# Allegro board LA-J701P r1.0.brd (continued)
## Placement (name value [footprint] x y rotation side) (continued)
PCB12  0.1U_0402_25V6  [C_0402]  48.06 3.45 180 bottom
PCB13  10U_0603_25V6M  [C_0603]  71.16 16.66 0 top
PCB14  10U_0603_25V6M  [C_0603]  71.16 15.39 0 top
PCB15  0.68U_0805_50V7K  [C_0805]  51.08 11.7 0 bottom
PCB16  1U_0402_25V6K  [C_0402]  51.92 5.38 0 bottom
PCB17  10U_0603_25V6M  [C_0603]  71.16 14.12 0 bottom
PCB18  2.2U_0402_10V6M  [C_0402]  48.03 11.82 180 bottom
PCB19  0.047U_0402_25V7K  [C_0402]  44.43 9.97 90 bottom
PCB20  680P_0402_50V7K  [C_0402]  63.48 4.72 90 top
PCB21  680P_0402_50V7K  [C_0402]  64.44 4.69 90 top
PCB22  0.1U_0402_25V6  [C_0402]  43.03 7.71 0 bottom
PCB23  0.1U_0402_25V6  [C_0402]  42.83 6.83 270 bottom
PCB24  0.1U_0402_25V6  [C_0402]  43.67 5.07 0 bottom
PCB25  100P_0402_50V8J  [C_0402]  51.74 4.46 0 bottom
PCB26  10U_0603_25V6M  [C_0603]  71.16 15.39 0 bottom
PCB27  10U_0603_25V6M  [C_0603]  71.16 16.66 0 bottom
PCB28  680P_0402_50V7K  [C_0402]  43.59 1.67 0 bottom
PCB29  15P_0402_50V8J  [C_0402]  44.42 3.52 270 bottom
PCB30  1800P_0402_50V7K  [C_0402]  45.34 1.66 0 bottom
PCB31  33P_0402_50V8J  [C_0402]  46.21 3.52 270 bottom
PCB32  100P_0402_50V8J  [C_0402]  51.31 3.57 0 bottom
PCB33  0.1U_0402_6.3V7K  [C_0402]  52.96 5.25 0 top
PCB34  1U_0402_25V6K  [C_0402]  76.03 6.01 270 top
PCB35  10U_0603_25V6M  [C_0603]  73.43 5.89 0 top
PCD1  4700P_0402_50V7K  [C_0402]  24.88 74.76 180 bottom
PCD2  100P_0402_50V8J  [C_0402]  32.67 74.19 0 bottom
PCD3  100P_0402_50V8J  [C_0402]  33.43 70.12 0 bottom
PCD4  1000P_0402_50V7K  [C_0402]  33.43 71.14 0 bottom
PCD5  2200P_0402_25V7K  [C_0402]  30.77 70.22 180 bottom
PCD6  0.1U_0402_25V6  [C_0402]  23.56 64.51 90 bottom
PCM1  22U_0603_6.3V6M  [C_0603]  146 38.98 180 bottom
PCM2  0.1U_0402_10V7K  [C_0402]  164.87 56.87 0 bottom
PCM3  22U_0603_6.3V6M  [C_0603]  150.37 32.19 0 bottom
PCM4  0.1U_0402_25V6  [C_0402]  158.27 39.79 270 top
PCM5  1U_0402_6.3V6K  [C_0402]  164.24 53.45 0 bottom
PCM6  22U_0603_6.3V6M  [C_0603]  146 36.57 180 bottom
PCM7  10U_0603_25V6M  [C_0603]  157.78 39.97 270 bottom
PCM8  22U_0603_6.3V6M  [C_0603]  150.37 33.39 0 bottom
PCM9  10U_0603_25V6M  [C_0603]  157.18 39.98 270 top
PCM10  1U_0402_6.3V6K  [C_0402]  163.38 50.32 90 bottom
PCM11  680P_0402_50V7K  [C_0402]  154.5 37.95 270 top
PCM12  2200P_0402_50V7K  [C_0402]  159.1 39.97 270 bottom
PCM13  0.1U_0402_10V7K  [C_0402]  164.24 55.95 0 bottom
PCM14  0.1U_0402_25V6  [C_0402]  157.56 52.57 0 bottom
PCM15  22U_0603_6.3V6M  [C_0603]  146 37.78 180 bottom
PCM16  22U_0603_6.3V6M  [C_0603]  150.37 34.6 0 bottom
PCM17  0.033U_0402_16V7K  [C_0402]  161.46 58.37 90 bottom
PCM18  10U_0402_6.3V6M  [C_0402]  159.17 58.12 0 bottom
PCM19  10U_0402_6.3V6M  [C_0402]  159.17 59.07 0 bottom
PCS1  2200P_0402_25V7K  [C_0402]  26.03 56.14 270 top
PD2  30MA_30V_0.5UA_0.4V_SOD323-2  [RB751V-40_SOD323-2]  84.32 11.97 90 top
PDB1  -  [BAT54CW_SOT323-3]  53.83 11.47 90 top
PDD1  -  [BZT52-B5V1S_SOD323-2]  29.95 60.41 90 bottom
PDM1  30MA_30V_0.5UA_0.4V_SOD323-2  [D_SOD323-2]  162.03 51.67 270 bottom
PF2  12A_24V_F1206HB12V024TM  [F_F1206HB12V024TM]  74.95 12.33 270 bottom
PFD1  7A_24V_F1206HI7000V024TM  [F_F1206HI7000V024TM]  28.22 74.95 0 bottom
PFS1  7A_24V_F1206HI7000V024TM  [F_F1206HI7000V024TM]  30.41 56.63 180 bottom
PH1  100K +-1% 0402 B25/50 4250K  [R_0402]  122.06 55.35 270 top
PH801  100K_0402_1%_B25/50 4250K  [R_0402]  111.67 93.1 90 bottom
PH802  100K_0402_1%_B25/50 4250K  [R_0402]  85.4 93.43 90 bottom
PJ251  -  [JUMP_43X79]  123.85 10.46 180 top
PJ252  -  [JUMP_43X79]  111.1 8.1 90 top
PJ301  -  [JUMP_43X79]  181.01 65.81 135 top
PJ302  -  [JUMP_43X118]  171.52 60.78 135 bottom
PJ303  -  [JUMP_43X39]  170.26 69.45 45 top
PJ501  -  [JUMP_43X118]  44.83 14.9 180 bottom
PJ502  -  [JUMP_43X118]  24.98 14.39 90 top
PJ503  -  [JUMP_43X39]  32.49 8.88 180 top
PJ601  -  [JUMP_43X118]  151.14 82.28 225 bottom
PJ604  -  [JUMP_43X79]  157.83 96.21 315 bottom
PJ1803  -  [JUMP_43X79]  173.18 87.74 225 bottom
PJ1804  -  [JUMP_43X79]  162.19 72.95 225 bottom
PJM1  -  [JUMP_43X79]  159.98 42.37 180 bottom
PJM2  -  [JUMP_43X118]  146.85 32.99 270 bottom
PJM3  -  [JUMP_43X39]  158.94 60.64 180 bottom
PL3  -  [5A_Z80_0805_2P]  73 5.31 270 bottom
PL4  -  [5A_Z80_0805_2P]  74.91 5.31 270 bottom
PL301  1.5UH_6A_20%_5X5X3_M  [L_5X5X3_M]  178.11 65.82 225 bottom
PL501  1.5UH_9A_20%_7X7X3_M  [L_7X7X3_M]  32.21 14.62 180 bottom
PL602  1UH_6.6A_20%_5X5X3_M  [L_5X5X3_M_2P]  156.21 90.01 225 bottom
PL801  NA_2P  [5A_Z80_0805_2P]  86.78 103.69 90 bottom
PL802  NA_2P  [5A_Z80_0805_2P]  88.62 103.69 90 bottom
PL803  0.24UH_22A_+-20%_7X7X3_M  [L_7X7X3_M]  81.14 96.9 270 bottom
PL804  0.15UH_NA__35A_20%  [L_7X7X3_M]  113.54 92.98 0 bottom
PL805  0.15UH_NA__35A_20%  [L_7X7X3_M]  130.34 95.63 270 bottom
PL806  0.15UH_NA__35A_20%  [L_7X7X3_M]  145.77 95.5 270 bottom
PL1802  1.5UH_TMPC0412HP-1R5M-Z02_3A_20%  [TAI-T_TMPC0412HP-1R5M-Z02_2P]  166.7 77.43 225 bottom
PLB1  2.2UH_PCMB103T-2R2MS_13A_20%  [CYNTE_PCMB103T-2R2MS_2P]  59.78 9.77 0 bottom
PLD11  -  [5A_Z80_0805_2P]  31.98 73 270 bottom
PLM1  1UH_6.6A_20%_5X5X3_M  [L_5X5X3_M]  149.48 36.47 90 bottom
PQ601  -  [LSK3541G1ET2L_VMT3]  166.21 90.84 135 top
PQ801  AON6994_DFN5X6D-8-7  [AON6962_DFN5X6D-8-7]  83.81 104.13 270 bottom
PQ802  -  [AON6962_DFN5X6D-8-7]  112.59 97.79 90 bottom
PQ804  -  [AON6962_DFN5X6D-8-7]  133.75 101.62 270 bottom
PQ805  -  [AON6962_DFN5X6D-8-7]  143.08 97.9 90 bottom
PQB1  AON6962_DFN5X6D-8-7  [AON6992_DFN5X6D-8-7]  57.26 11.7 270 top
PQB2  -  [AON6994_DFN5X6D-8-7]  70.5 7.89 90 top
PQB3  -  [LSK3541G1ET2L_VMT3]  53.47 7.26 0 top
PQB4  -  [LSK3541G1ET2L_VMT3]  54.69 4.79 90 top
PQB13  AONR21357_P_DFN33-8-5  [Q_P_DFN33-8-5]  72.44 12.42 270 top
PQD3  -  [2N7002KDW_SOT363-6]  25.87 64.46 180 bottom
PQD4  TP0610K-T1-GE3 1P SOT23-3  [LBSS84LT1G_SOT23-3]  29.98 65.17 270 bottom
PQD5  -  [METR3906KW-G_SOT363-6]  26.31 61.47 0 bottom
PQD11  AONR21357_P_DFN33-8-5  [Q_P_DFN33-8-5]  32.27 68.56 0 bottom
PQD12  AONR21357_P_DFN33-8-5  [Q_P_DFN33-8-5]  34.23 60.75 180 bottom
PQM1  -  [AON7408L_DFN8-5]  153.29 40.49 90 bottom
PQM2  -  [AON7506_DFN3X3-8-5]  156.16 38.6 270 bottom
PQS2  L2N7002SWT1G 1N SC-70-3  [L2N7002WT1G_SC70-3]  26.08 52.88 180 top
PQS3  TP0610K-T1-GE3 1P SOT23-3  [LBSS84LT1G_SOT23-3]  29.68 53.06 180 top
PQS4  -  [METR3906KW-G_SOT363-6]  32.41 50.95 0 top
PQS11  AONR21357_P_DFN33-8-5  [Q_P_DFN33-8-5]  28.33 57.44 270 top
PQS12  AONR21357_P_DFN33-8-5  [Q_P_DFN33-8-5]  36.04 55.47 90 top
PR8  0_0603_5%  [R0603_0OHM]  81.77 12.21 180 top
PR9  45.3K_0603_1%  [R_0603]  81.58 13.48 0 top
PR10  0_0603_5%  [R0603_0OHM]  81.79 11.01 180 top
PR11  100_0402_1%  [R_0402]  82.88 15.73 90 bottom
PR12  100_0402_1%  [R_0402]  81.92 15.73 90 bottom
PR13  16.5K_0402_1%  [R_0402]  122.07 57.24 270 top
PR14  200K_0402_1%  [R_0402]  85.11 15.65 180 bottom
PR15  10K_0402_5%  [R_0402]  85.11 16.44 180 bottom
PR251  0_0402_5%  [R0402_0OHM]  126.25 8.51 180 top
PR252  43K_0402_1%  [R_0402]  113.86 8.57 0 top
PR254  20K_0402_1%  [R_0402]  114.77 7.78 180 top
PR256  0_0402_5%  [R_0402]  126.28 7.7 180 top
PR301  0_0402_5%  [R0402_0OHM]  177.32 65.51 315 top
PR302  4.7_1206_5%  [R_1206]  176.31 62.68 225 top
PR303  100K_0402_5%  [R_0402]  177.58 71.07 225 top
PR304  1K_0402_1%  [R_0402]  172.39 70.78 315 top
PR501  0_0402_5%  [R0402_0OHM]  35.11 16.74 90 bottom
PR502  4.7_0805_5%  [R_0805]  31.72 12.46 270 top
PR503  0_0402_5%  [R_0402]  39.23 8.9 90 bottom
PR504  499K_0402_1%  [R_0402]  178.29 72.15 135 top
PR505  1K_0402_1%  [R_0402]  38.12 10.22 180 bottom
PR506  150K_0402_1%  [R_0402]  177.05 71.64 135 top
PR507  100K_0402_5%  [R_0402]  171.23 68.28 225 top
PR508  0_0402_5%  [R0402_0OHM]  169.36 65.14 135 top
PR509  2.2K_0402_5%  [R_0402]  172.29 72.34 225 top
PR510  0_0402_5%  [R0402_0OHM]  173.73 73.35 225 top
PR511  100K_0402_5%  [R_0402]  169.28 66.34 315 top
PR512  1M_0402_1%  [R_0402]  173.69 72.1 45 top
PR601  0_0402_5%  [R0402_0OHM]  166.27 90.84 135 bottom
PR602  4.7_1206_5%  [R_1206]  153.44 92.82 225 bottom
PR603  0_0603_5%  [R0603_0OHM]  157.31 92.73 135 bottom
PR604  0_0402_5%  [R0402_0OHM]  160.73 87.44 225 bottom
PR605  0_0402_5%  [R_0402]  163.76 89.62 315 bottom
PR606  10K_0402_1%  [R_0402]  163.18 89.03 315 bottom
PR607  1M_0402_1%  [R_0402]  164.39 90.25 315 bottom
PR609  36.5K_0402_1%  [R_0402]  162.61 88.47 315 bottom
PR610  10_0402_1%  [R_0402]  153.53 78.99 315 bottom
PR611  1K_0402_1%  [R_0402]  161.19 84.25 315 bottom
PR621  0_0402_5%  [R_0402]  165.39 92.01 45 top
PR622  0_0402_5%  [R_0402]  164.67 89.5 45 top
PR623  0_0402_5%  [R_0402]  166.84 91.4 135 bottom
PR713  0_0402_5%  [R0402_0OHM]  167.42 80.68 135 bottom
PR716  1K_0402_1%  [R_0402]  172.71 76.37 135 bottom
PR719  0_0402_5%  [R_0402]  169.32 76.81 45 top
PR720  0_0402_5%  [R0402_0OHM]  169.42 77.99 225 top
PR801  10_0402_5%  [R_0402]  106.87 94.49 90 bottom
PR802  10_0402_5%  [R_0402]  104.46 95.33 270 bottom
PR803  0_0603_5%  [R0603_0OHM]  84.94 103.97 180 top
PR804  2.2_0603_5%  [R_0603]  94.12 103.02 90 bottom
PR805  10K_0402_1%  [R_0402]  103.67 95.33 270 bottom
PR806  63.4K_0402_1%  [R_0402]  102.43 94.8 270 bottom
PR807  105K_0402_1%  [R_0402]  104.04 102.19 0 bottom
PR808  4.7_1206_5%  [R_1206]  81.84 97.77 180 top
PR809  2.43K_0402_1%  [R_0402]  91.23 98.71 0 top
PR810  845_0402_1%  [R_0402]  92.18 97.76 180 bottom
PR811  2.2_0402_5%  [R_0402]  101.24 101.66 0 top
PR812  10_0603_5%  [R_0603]  92.22 91.27 180 bottom
PR815  0_0402_5%  [R0402_0OHM]  94.86 90.63 90 bottom
PR816  9.31K_0402_1%  [R_0402]  101.07 91.6 180 bottom
PR817  0_0603_5%  [R0603_0OHM]  110.93 96.35 0 bottom
PR818  8.25K_0402_1%  [R_0402]  96.62 91.54 180 bottom
PR819  100K_0402_1%  [R_0402]  92.12 101.25 180 bottom
PR820  2.2_0603_5%  [R_0603]  102.21 103.03 90 bottom
PR821  11.5K_0402_1%  [R_0402]  100.18 90.74 0 bottom
PR822  11.8K_0402_1%  [R_0402]  96.62 90.71 180 bottom
PR823  14.3K_0402_1%  [R_0402]  97.58 91.44 180 top
PR824  4.7_1206_5%  [R_1206]  115.51 95.67 0 top
PR825  15K_0402_1%  [R_0402]  100.12 91.48 0 top
PR826  2K_0402_1%  [R_0402]  104.97 101.43 180 bottom
PR827  100K_0402_1%  [R_0402]  94.59 95.6 0 top
PR828  100K_0402_5%  [R_0402]  92.12 100.43 180 bottom
PR829  10K_0402_5%  [R_0402]  92.12 99.6 180 bottom
PR830  1.1K_0402_1%  [R_0402]  104.09 99.75 0 bottom
PR831  59K_0402_1%  [R_0402]  91.25 93.36 90 bottom
PR832  10K_0402_1%  [R_0402]  91.25 95.08 90 bottom
PR833  10_0402_5%  [R_0402]  91.23 96.87 0 top
PR834  13.7K_0402_1%  [R_0402]  91.41 92.92 0 top
PR835  205K_0402_1%  [R_0402]  94 91.52 270 bottom
PR836  470_0402_1%  [R_0402]  93.13 90.56 90 top
PR837  33K_0402_1%  [R_0402]  93.18 91.52 270 bottom
PR838  0_0603_5%  [R0603_0OHM]  132.08 103.09 0 bottom
PR839  2.2_0603_5%  [R_0603]  96.81 103.02 90 bottom
PR840  4.7_1206_5%  [R_1206]  133.3 96.63 180 top
PR841  2K_0402_1%  [R_0402]  104.92 97.92 180 top
PR842  1.1K_0402_1%  [R_0402]  104.16 98.84 0 bottom
PR843  0_0402_5%  [R_0402]  104.05 96.25 0 top
PR844  0_0402_5%  [R0402_0OHM]  104.11 96.37 0 bottom
PR845  0_0402_5%  [R_0402]  103.99 97.11 0 top
PR846  0_0402_5%  [R0402_0OHM]  104.11 97.17 0 bottom
PR847  0_0402_5%  [R0402_0OHM]  147.8 103.68 90 bottom
PR853  0_0603_5%  [R_0603]  143.02 99.37 270 top
PR855  4.7_1206_5%  [R_1206]  145.08 95.27 0 top
PR856  2K_0402_1%  [R_0402]  109.03 96.37 90 top
PR857  1.1K_0402_1%  [R_0402]  105.74 96.26 0 top
PR858  24.3K_0402_1%  [R_0402]  99.3 90.54 90 top
PR859  21.5K_0402_1%  [R_0402]  97.44 90.67 90 bottom
PR860  2.2_0603_5%  [R_0603]  145.57 103.2 180 bottom
PR871  0_0402_5%  [R_0402]  51.65 2.37 0 bottom
PR1807  0_0402_5%  [R0402_0OHM]  173.95 77.63 135 top
PR1808  20K_0402_1%  [R_0402]  171.52 76.43 225 bottom
PR1809  10K_0402_1%  [R_0402]  172.7 77.62 315 bottom
PR1810  2.2_0603_5%  [R_0603]  165.38 80.15 225 bottom
PR1811  1M_0402_1%  [R_0402]  173.96 78.97 315 bottom
PR1812  100K_0402_1%  [R_0402]  169.47 74.57 315 bottom
PR1813  0_0402_5%  [R0402_0OHM]  93.06 92.92 0 top
PR1814  2.2_0402_1%  [R_0402]  105.96 103.85 270 bottom
PR1815  2.2_0402_1%  [R_0402]  99.8 92.84 90 top
PR1816  0_0402_5%  [R0402_0OHM]  94.97 92.84 90 top
PR1817  0_0402_5%  [R0402_0OHM]  96.94 94.51 270 top
PR1818  0_0402_5%  [R_0402]  96.18 94.51 270 top
PR1819  0_0402_5%  [R_0402]  92.74 93.68 0 top
PRB1  0.01_1206_1%  [R_1206_4P-D]  55.35 6.11 90 top
PRB2  4.99_0402_1%  [R_0402]  53.65 8.4 180 top
PRB3  4.99_0402_1%  [R_0402]  53.65 9.8 180 top
PRB4  0_0402_5%  [R0402_0OHM]  49.13 12.41 270 bottom
PRB5  511K_0402_1%  [R_0402]  48.06 1.67 180 bottom
PRB6  10_0402_1%  [R_0402]  51.26 5.66 0 top
PRB7  75K_0402_1%  [R_0402]  48.06 2.56 180 bottom
PRB8  1_0805_5%  [R_0805]  52.61 11.7 180 top
PRB9  0.01_1206_1%  [R_1206_4P-D]  75.81 7.64 180 top
PRB10  0_0402_5%  [R0402_0OHM]  50.56 2.49 180 bottom
PRB11  0_0402_5%  [R0402_0OHM]  45.37 11.85 0 bottom
PRB12  0_0402_5%  [R0402_0OHM]  50.57 1.59 180 bottom
PRB13  0_0402_5%  [R_0402]  50.52 3.52 180 bottom
PRB14  4.7_1206_5%  [R_1206]  59.6 5.05 0 top
PRB15  4.7_1206_5%  [R_1206]  68.32 5.05 180 top
PRB16  100K_0402_5%  [R_0402]  51.82 8.76 90 top
PRB17  100K_0402_5%  [R_0402]  51.06 8.43 180 top
PRB18  10_0402_1%  [R_0402]  43.67 6.85 0 bottom
PRB19  10_0402_1%  [R_0402]  43.67 5.96 0 bottom
PRB20  137K_0402_1%  [R_0402]  51.74 4.39 0 top
PRB21  10K_0402_1%  [R_0402]  43.54 3.52 270 bottom
PRB22  100K_0402_1%  [R_0402]  48.71 5.57 0 top
PRB23  82K_0402_1%  [R_0402]  50.52 6.83 270 top
PRB24  100K_0402_1%  [R_0402]  53.95 7.51 0 bottom
PRB25  165K_0402_1%  [R_0402]  52.35 6.22 90 bottom
PRB26  40.2K_0402_1%  [R_0402]  45.32 3.52 270 bottom
PRB27  100K_0402_1%  [R_0402]  51.31 6.85 0 top
PRB28  100K_0402_1%  [R_0402]  51.06 7.64 180 top
PRB29  100K_0402_5%  [R_0402]  54.16 3.62 180 bottom
PRB30  0_0402_5%  [R_0402]  53.14 6.22 90 bottom
PRB31  100K_0402_5%  [R_0402]  53.62 5.35 0 bottom
PRB32  0_0402_5%  [R0402_0OHM]  72.14 13.07 180 bottom
PRB33  100K_0402_5%  [R_0402]  47.88 5.28 270 top
PRB34  100K_0402_5%  [R_0402]  49.55 4.42 180 top
PRD1  499K_0402_1%  [R_0402]  30.79 69.31 180 bottom
PRD2  49.9K_0402_1%  [R_0402]  30 68.42 180 bottom
PRD3  47K_0402_1%  [R_0402]  25.27 60.31 180 bottom
PRD4  470K_0402_1%  [R_0402]  25.27 59.45 180 bottom
PRD5  47K_0402_1%  [R_0402]  28.55 60.9 90 bottom
PRD6  154K_0402_1%  [R_0402]  24.13 62.32 90 bottom
PRD7  24K_0402_1%  [R_0402]  24.98 63.23 0 bottom
PRD8  100K_0402_5%  [R_0402]  25.33 67.14 180 bottom
PRD9  470K_0402_1%  [R_0402]  28.5 62.63 180 bottom
PRM1  4.7_1206_5%  [R_1206]  151.81 39.45 0 top
PRM2  6.04K_0402_1%  [R_0402]  163.17 58.36 90 bottom
PRM3  0_0402_5%  [R0402_0OHM]  165.15 55.06 180 bottom
PRM4  0_0402_5%  [R0402_0OHM]  165.78 57.74 180 bottom
PRM5  23.7K_0402_1%  [R_0402]  160.73 50.3 90 bottom
PRM6  5.1_0603_5%  [R_0603]  165.73 52.37 180 bottom
PRM8  2.2_0603_5%  [R_0603]  165.7 51.14 180 bottom
PRM9  10K_0402_1%  [R_0402]  164 58.36 90 bottom
PRM10  470K_0402_1%  [R_0402]  165.15 54.27 180 bottom
PRM11  2.2_0603_5%  [R_0603]  157.33 53.55 90 bottom
PRM12  10_0402_5%  [R_0402]  162.36 59.29 270 bottom
PRM13  0_0402_5%  [R_0402]  163.16 60.06 90 bottom
PRM14  0_0402_5%  [R_0402]  163.99 60.06 90 bottom
PRS1  499K_0402_1%  [R_0402]  26.97 56.17 270 top
PRS2  49.9K_0402_1%  [R_0402]  26.92 53.98 180 top
PRS4  47K_0402_1%  [R_0402]  32.44 53.87 180 top
PRS5  470K_0402_1%  [R_0402]  33.3 53.87 0 top
PRS6  47K_0402_1%  [R_0402]  34.74 50.96 0 top
PU251  -  [RT9059GQW_WDFN10_3X3]  116.2 9.8 270 top
PU301  -  [SY8388BRHC_QFN16_2P5X2P5]  176.26 66.35 135 top
PU501  -  [SY8288CRAC_QFN20_3X3]  35.34 15.47 270 bottom
PU601  -  [SY8284RAC_QFN20_3X3]  158.92 92.14 315 bottom
PU801  RT3663BMGQW_WQFN52_6X6  [RT3663BHGQW_WQFN52_6X6]  100.54 99.39 180 bottom
PU802  -  [RT9610CGQW_WDFN8_2X2]  145.63 104.45 270 top
PU1802  -  [SY8386RHC_QFN16_2P5X2P5]  168.54 79.89 315 bottom
PUB1  BQ25710RSNR_QFN32_4X4  [BQ25700ARSNR_QFN32_4X4]  50.44 8.78 180 bottom
PUM1  -  [RT8207PGQW_WQFN20_3X3]  160.53 56.51 0 bottom
Q5  ME2320D-G 1N SOT-23-3  [LBSS138LT1G_SOT23-3]  159.59 70.1 315 bottom
Q146  -  [2N7002KW_SOT323-3]  160.36 66.36 135 bottom
Q201  -  [ME2301DC-G_SOT23-3]  56.47 64.92 270 top
Q202  -  [2N7002KDW_SOT363-6]  181.23 55.77 270 bottom
Q206  -  [LBSS139WT1G_SC70-3]  57.06 61.49 90 top
Q207  -  [LBSS139WT1G_SC70-3]  57.06 58.95 90 top
Q208  -  [ME2301DC-G_SOT23-3]  32.62 50.77 90 bottom
Q209  -  [ME2301DC-G_SOT23-3]  45.09 48.28 270 bottom
QA1  -  [ME2301DC-G_SOT23-3]  21.29 50.5 90 bottom
QA2  -  [ME2301DC-G_SOT23-3]  18.77 28.05 0 bottom
QA3  -  [ME2301DC-G_SOT23-3]  21.29 54.56 90 bottom
QA4  -  [2N7002KDW_SOT363-6]  17.81 22.23 0 bottom
QC1  -  [LBSS139WT1G_SC70-3]  78.4 57.55 90 top
QC2  -  [2N7002KDW_SOT363-6]  62.81 88.68 270 top
QH1  -  [2N7002KDW_SOT363-6]  17.74 70.97 0 top
QH2  2N7002KDW_SC88-6  [2N7002DW-T-R7_SOT363-6]  24.38 70.91 180 bottom
QKBL1  -  [ME2301DC-G_SOT23-3]  144.67 15.96 90 bottom
QT1  2N7002K_SOT23-3  [2N7002_SOT23-3]  18.3 77.5 180 top
QT2  -  [2N7002KW_SOT323-3]  30.42 69.36 270 top
QT3  -  [ME2301DC-G_SOT23-3]  42.75 78.5 270 top
QT4  -  [L2N7002WT1G_SC-70-3]  45.51 73.42 270 top
QTP1  -  [ME2301DC-G_SOT23-3]  121.92 8.4 270 bottom
QTS1  -  [MMST3904-7-F_SOT323-3]  74.53 17.54 90 bottom
QTS2  -  [MMST3904-7-F_SOT323-3]  19.98 47.25 0 bottom
QTS3  -  [MMST3904-7-F_SOT323-3]  98.56 88.09 90 bottom
R2  0_0805_5%  [R0805_0OHM]  54.21 70.41 90 top
R5  0_0402_5%  [R0402_0OHM]  58.65 76.42 270 top
R6  0_0402_5%  [R0402_0OHM]  53.39 74.57 180 top
R7  100K_0402_5%  [R_0402]  58.65 73.86 90 top
R8  100K_0402_5%  [R_0402]  54.38 74.57 0 top
R9  0_0805_5%  [R0805_0OHM]  50.97 78.01 0 top
R54  10K_0402_5%  [R_0402]  195.74 28.97 0 top
R55  100K_0402_5%  [R_0402]  182.35 47.44 90 top
R56  10K_0402_5%  [R_0402]  192.94 40.79 0 top
R57  10K_0402_5%  [R_0402]  186.03 47.44 90 top
R58  10_0402_5%  [R_0402]  173.66 39.39 180 top
R59  4.7K_0402_5%  [R_0402]  185.14 49.6 90 top
R60  47K_0402_5%  [R_0402]  179.11 27.78 270 top
R62  2.2K_0402_5%  [R_0402]  81.02 4.46 180 top
R63  2.2K_0402_5%  [R_0402]  81.02 5.28 180 top
R64  10K_0402_5%  [R_0402]  173.21 34.46 90 top
R65  100K_0402_5%  [R_0402]  193.77 31.76 180 top
R66  100K_0402_5%  [R_0402]  184.13 48.35 270 top
R67  100K_0402_5%  [R_0402]  189.72 48.35 270 top
R68  100K_0402_5%  [R_0402]  180.57 48.35 270 top
R69  100K_0402_5%  [R_0402]  193.98 43.64 180 top
R70  100K_0402_5%  [R_0402]  191 48.39 270 top
R74  100K_0402_1%  [R_0402]  182.39 54.23 90 bottom
R75  22_0603_1%  [R_0603]  178.24 57.08 0 bottom
R185  10K_0402_5%  [R_0402]  159.05 66.13 225 bottom
R201  150K_0402_5%  [R_0402]  60.94 64.86 270 top
R265  866_0402_1%  [R_0402]  182.01 22.59 270 top
R266  866_0402_1%  [R_0402]  158.42 25.48 180 bottom
R267  866_0402_1%  [R_0402]  177.46 27.72 270 top
R273  2.2K_0402_5%  [R_0402]  196.65 31.64 180 top
R274  2.2K_0402_5%  [R_0402]  196.65 32.4 180 top
R337  0_0603_5%  [R_0603]  47.17 62.84 0 top
R358  HCB1005KF-221T15  [MURAT_BLM15PX221SN1D_2P]  53.36 59.33 180 top
R359  0_0402_5%  [R0402_0OHM]  50.19 57.8 0 top
R360  0_0402_5%  [R_0402]  50.19 58.69 0 top
R2752  47K_0402_5%  [R_0402]  159.62 65.56 225 bottom
R3999  0_0402_5%  [R0402_0OHM]  177.91 47.44 90 top
R4000  0_0603_5%  [R0603_0OHM]  194.35 45.55 180 top
R4002  0_0402_5%  [R0402_0OHM]  187.05 47.44 90 top
R4006  100K_0402_5%  [R_0402]  57 78.2 270 top
R4007  100K_0402_5%  [R_0402]  61.83 63.95 90 top
R4010  10K_0402_5%  [R_0402]  179.68 47.44 90 top
R4011  10K_0402_5%  [R_0402]  178.79 47.44 90 top
R4012  10K_0402_5%  [R_0402]  175.56 46.79 90 top
R4014  1K_0402_5%  [R_0402]  54.21 58.68 90 top
R4015  10K_0402_5%  [R_0402]  51.63 54.2 270 top
R4020  10K_0402_5%  [R_0402]  172.22 31.16 180 top
R4021  4.7_1206_5%  [R_1206]  34.52 77.87 180 top
R4022  10K_0402_5%  [R_0402]  192.6 47.48 90 top
R4023  10K_0402_5%  [R_0402]  192.98 34.83 270 top
R4024  0_0402_5%  [R_0402]  55.92 62.32 270 top
R4025  0_0402_5%  [R_0402]  56.76 60.53 180 top
R4026  100K_0402_5%  [R_0402]  200.71 31.01 180 top
RA1  0_0603_5%  [R0603_0OHM]  28.83 5.74 90 bottom
RA2  33_0402_5%  [R_0402]  3.74 33.65 0 bottom
RA3  0_0603_5%  [R0603_0OHM]  22.6 6.8 90 bottom
RA4  33_0402_5%  [R_0402]  6.35 30.98 180 bottom
RA5  0_0603_5%  [R0603_0OHM]  28.35 2.27 180 bottom
RA6  0_0603_5%  [R0603_0OHM]  22.34 4.51 270 bottom
RA8  0_0402_5%  [R0402_0OHM]  10.16 30.93 0 bottom
RA9  10K_0402_5%  [R_0402]  11.41 40.66 90 bottom
RA10  2.2K_0402_5%  [R_0402]  9.63 41.45 180 bottom
RA11  2.2K_0402_5%  [R_0402]  7.5 41.55 270 bottom
RA12  0_0805_5%  [R0805_0OHM]  16.17 32.17 270 bottom
RA13  BLM15BD121SN1D_2P  [MURAT_BLM15BD121SN1D_2P]  10.79 42.13 180 top
RA14  BLM15BD121SN1D_2P  [MURAT_BLM15BD121SN1D_2P]  10.79 41.22 180 top
RA15  47_0402_5%  [R_0402]  7.01 44.98 0 bottom
RA16  47_0402_5%  [R_0402]  6.18 45 180 bottom
RA17  10K_0402_5%  [R_0402]  7.93 44.16 180 bottom
RA18  10K_0402_5%  [R_0402]  5.26 44.19 0 bottom
RA19  0_0603_5%  [R0603_0OHM]  14.01 36.59 125.1 top
RA21  0_0402_5%  [R0402_0OHM]  12.75 33.94 180 top
RA22  0_0402_5%  [R0402_0OHM]  16.82 54.42 90 bottom
RA23  0_0402_5%  [R0402_0OHM]  15.93 54.42 90 bottom
RA24  33K_0402_5%  [R_0402]  13.82 53.28 90 bottom
RA25  0_0402_5%  [R0402_0OHM]  3.79 36.34 90 bottom
RA26  0_0402_5%  [R0402_0OHM]  4.22 46.26 90 top
RA27  4.7K_0402_5%  [R_0402]  16.64 44.47 180 bottom
RA28  0_0402_5%  [R0402_0OHM]  2.68 39.4 0 top
RA29  4.7K_0402_5%  [R_0402]  16.64 45.26 180 bottom
RA30  0_0402_5%  [R_0402]  15.73 46.04 0 bottom
RA31  0_0402_5%  [R0402_0OHM]  17.09 51.57 180 top
RA32  0_0402_5%  [R0402_0OHM]  16.11 58.62 270 top
RA33  0_0402_5%  [R0402_0OHM]  13.38 30.55 90 bottom
RA34  0_0603_5%  [R0603_0OHM]  11.28 34.94 0 top
RA51  150K_0402_5%  [R_0402]  25.06 51.44 90 bottom
RA54  47K_0402_5%  [R_0402]  16.74 20.85 90 bottom
RA55  150K_0402_5%  [R_0402]  21.06 22.48 90 bottom
RA57  47K_0402_5%  [R_0402]  25.06 54.55 90 bottom
RA58  0_0402_5%  [R_0402]  19.54 50.45 270 bottom
RA59  0_0603_5%  [R_0603]  15.85 29.04 0 bottom
RA60  0_0402_5%  [R_0402]  19.54 54.58 270 bottom
RA61  47K_0402_5%  [R_0402]  20.23 22.48 90 bottom
RC1  1K_0402_5%  [R_0402]  112.69 44.85 90 bottom
RC2  1K_0402_5%  [R_0402]  113.58 58.76 270 top
RC4  4.7K_0402_5%  [R_0402]  80.75 64.29 270 top
RC5  2.2K_0402_5%  [R_0402]  77.32 57.35 90 top
RC6  100K_0402_5%  [R_0402]  81.39 58.2 270 top
RC8  100K_0402_5%  [R_0402]  86.8 59.2 180 bottom
RC9  100K_0402_5%  [R_0402]  77.45 61.5 270 top
RC10  100K_0402_5%  [R_0402]  86.9 67.81 180 bottom
RC11  10K_0402_5%  [R_0402]  90.73 56.6 180 top
RC12  10K_0402_5%  [R_0402]  90.73 55.33 180 top
RC13  10K_0402_5%  [R_0402]  90.73 57.42 180 top
RC14  10K_0402_5%  [R_0402]  90.73 54.37 180 top
RC15  1K_0402_5%  [R_0402]  87.05 56.6 180 top
RC16  1K_0402_5%  [R_0402]  87.05 55.71 180 top
RC17  1K_0402_5%  [R_0402]  84.57 58.37 180 bottom
RC18  1K_0402_5%  [R_0402]  86.8 58.37 180 bottom
RC21  0_0402_5%  [R0402_0OHM]  135.06 66.06 180 bottom
RC22  196_0402_1%  [R_0402]  98.8 73.16 180 top
RC24  4.7K_0402_5%  [R_0402]  139.63 81.43 180 bottom
RC25  4.7K_0402_5%  [R_0402]  121.23 80.12 270 bottom
RC28  1K_0402_5%  [R_0402]  84.67 53.23 90 bottom
RC29  1K_0402_5%  [R_0402]  132.69 65.22 90 bottom
RC30  220_0402_5%  [R_0402]  120.34 78.99 180 bottom
RC31  1K_0402_5%  [R_0402]  85.25 60.84 0 bottom
RC34  33_0402_5%  [R_0402]  142.85 63.82 90 bottom
RC35  33_0402_5%  [R_0402]  140.73 64.29 90 bottom
RC36  22K_0402_5%  [R_0402]  137.23 72.54 0 bottom
RC45  10K_0402_5%  [R_0402]  83.96 65.41 180 bottom
RC47  10K_0402_5%  [R_0402]  137.61 63.76 90 bottom
RC48  10K_0402_5%  [R_0402]  135.09 65.23 0 bottom
RC50  1K_0402_5%  [R_0402]  116.03 79.71 270 bottom
RC53  10K_0402_5%  [R_0402]  115.47 80.49 135 bottom
RC54  10K_0402_5%  [R_0402]  116.84 79.33 270 bottom
RC55  8.2K_0402_5%  [R_0402]  172.03 43.34 270 top
RC56  2.2K_0402_5%  [R_0402]  134.37 64.46 180 bottom
RC57  2.2K_0402_5%  [R_0402]  134.36 62.76 180 bottom
RC59  10K_0402_5%  [R_0402]  133.72 73.59 0 bottom
RC60  10K_0402_5%  [R_0402]  113.64 80.31 180 bottom
RC62  4.7K_0402_5%  [R_0402]  66.27 84.97 90 top
RC63  100K_0402_5%  [R_0402]  65.52 85.62 180 top
RC64  0_0402_5%  [R0402_0OHM]  168.19 42.35 270 top
RC65  2K_0402_5%  [R_0402]  133.72 74.43 0 bottom
RC66  2K_0402_5%  [R_0402]  112.73 78.5 0 bottom
RC67  33_0402_5%  [R_0402]  115.82 81.31 315 bottom
RC68  33_0402_5%  [R_0402]  135.37 74.45 0 bottom
RC69  33_0402_5%  [R_0402]  88.61 77.4 0 top
RC70  1K_0402_5%  [R_0402]  88.61 76.61 0 top
RC71  1K_0402_5%  [R_0402]  137.94 74.45 180 bottom
RC72  10K_0402_5%  [R_0402]  163.94 36.8 270 top
RC73  0_0402_5%  [R0402_0OHM]  165.26 34.56 0 top
RC74  33_0402_5%  [R_0402]  128.49 76.38 180 bottom
RC75  1M_0402_5%  [R_0402]  129.25 77.25 270 bottom
RC76  33_0402_5%  [R_0402]  128.49 77.2 180 bottom
RC77  10_0402_5%  [R_0402]  127.56 63.65 180 bottom
RC78  10_0402_5%  [R_0402]  128.32 66.63 180 bottom
RC79  10_0402_5%  [R_0402]  138.27 68.76 180 bottom
RC80  10_0402_5%  [R_0402]  128.58 67.39 180 bottom
RC81  22_0402_5%  [R_0402]  128.34 65.41 180 bottom
RC82  33_0402_5%  [R_0402]  128.13 69.86 180 bottom
RC83  100K_0402_5%  [R_0402]  172.7 37.48 0 top
RC84  10_0402_1%  [R_0402]  132.07 72.92 180 bottom
RC85  10K_0402_5%  [R_0402]  137.46 62.13 180 bottom
RC86  20M_0402_5%  [R_0402]  127.7 78.26 180 top
RC87  22 +-5% 0402  [R_0402]  140.38 62.84 270 bottom
RC89  10K_0402_5%  [R_0402]  83.02 67.01 0 bottom
RC90  10K_0402_5%  [R_0402]  134.38 60.33 90 bottom
RC91  10K_0402_5%  [R_0402]  189.32 16.4 0 top
RC92  10K_0402_5%  [R_0402]  140.69 43.66 270 bottom
RC93  10K_0402_5%  [R_0402]  138.15 54.3 90 bottom
RC94  10K_0402_5%  [R_0402]  139.42 54.3 90 bottom
RC95  10K_0402_5%  [R_0402]  137.01 54.3 90 bottom
RC96  10K_0402_5%  [R_0402]  138.15 43.66 270 bottom
RC97  10_0402_5%  [R_0402]  131.16 73.68 0 bottom
RC98  100K_0402_5%  [R_0402]  137.63 77.28 270 bottom
RC99  100K_0402_5%  [R_0402]  138.4 77.28 270 bottom
RC106  0_0402_5%  [R0402_0OHM]  88.19 6.62 180 top
RC107  1K_0402_5%  [R_0402]  86.29 4.59 180 top
RC111  0_0402_5%  [R_0402]  137.39 80.74 270 bottom
RC112  10K_0402_5%  [R_0402]  143.93 60.51 90 bottom
RC115  10K_0402_5%  [R_0402]  143.12 58.73 90 bottom
RC119  10K_0402_5%  [R_0402]  144.92 83.86 90 top
RC120  10K_0402_5%  [R_0402]  145.7 83.86 90 top
RC121  10K_0402_5%  [R_0402]  145.71 81.56 90 top
RC122  10K_0402_5%  [R_0402]  144.94 81.56 90 top
RC123  10K_0402_5%  [R_0402]  120.92 67.7 0 top
RC124  10K_0402_5%  [R_0402]  126.2 66.63 180 top
RC560  10K_0402_5%  [R_0402]  126.2 67.42 180 top
RC561  10K_0402_5%  [R_0402]  122.62 67.9 270 top
RC568  10K_0402_5%  [R_0402]  143.04 60.51 90 bottom
RC569  10K_0402_5%  [R_0402]  142.23 58.73 90 bottom
RC574  10K_0402_5%  [R_0402]  83.02 67.82 0 bottom
RC585  0_0402_5%  [R0402_0OHM]  131.17 64.46 0 bottom
RC586  0_0402_5%  [R0402_0OHM]  131.17 63.57 0 bottom
RC593  10K_0402_5%  [R_0402]  132.05 74.63 180 bottom
RC594  0_0402_5%  [R0402_0OHM]  90.76 59.43 180 top
RC595  0_0402_5%  [R0402_0OHM]  90.76 58.66 180 top
RC597  0_0402_5%  [R0402_0OHM]  140.62 72.46 0 bottom
RC598  0_0402_5%  [R_0402]  166.42 28.21 180 top
RC601  10K_0402_5%  [R_0402]  88.61 75.82 0 top
RC602  0_0402_5%  [R_0402]  83.79 54.15 270 bottom
RC603  0_0402_5%  [R0402_0OHM]  124.1 80.4 270 bottom
RC604  0_0402_5%  [R0402_0OHM]  127.27 69.98 180 top
RC605  0_0402_5%  [R_0402]  126.28 69.12 270 top
RC606  10K_0402_5%  [R_0402]  88.64 75.04 0 top
RC607  10K_0402_5%  [R_0402]  88.64 74.25 0 top
RC608  4.7K_0402_5%  [R_0402]  84.59 72.2 0 top
RC609  4.7K_0402_5%  [R_0402]  87.15 72.2 180 top
RC610  2.2K_0402_5%  [R_0402]  139.56 63.71 270 bottom
RC611  10K_0402_5%  [R_0402]  122.71 79.85 270 bottom
RC614  10K_0402_5%  [R_0402]  129.91 71.13 0 bottom
RC615  10K_0402_5%  [R_0402]  128.13 71.1 0 bottom
RC616  10K_0402_5%  [R_0402]  130.83 71.91 180 bottom
RC617  0_0402_5%  [R0402_0OHM]  144.42 62.18 90 bottom
RC618  4.7K_0402_5%  [R_0402]  85.49 73.93 270 top
RC619  4.7K_0402_5%  [R_0402]  86.25 73.93 270 top
RC620  10K_0402_5%  [R_0402]  83.05 66.2 0 bottom
RC621  10K_0402_5%  [R_0402]  131.14 75.42 0 bottom
RC624  2.2K_0402_5%  [R_0402]  134.36 65.23 180 bottom
RC625  2.2K_0402_5%  [R_0402]  134.37 63.57 180 bottom
RC626  0_0402_5%  [R0402_0OHM]  86.22 6.46 90 top
RC627  0_0402_5%  [R0402_0OHM]  114.34 60.18 180 top
RC628  0_0402_5%  [R_0402]  63.78 86.44 0 top
RD1  1K_0402_5%  [R_0402]  87.34 12.73 0 top
RD2  39_0402_5%  [R_0402]  87.34 13.49 0 top
RD3  39_0402_5%  [R_0402]  90.39 14.75 0 top
RD4  39_0402_5%  [R_0402]  87.34 17.51 0 top
RD5  39_0402_5%  [R_0402]  90.39 13.16 0 top
RD6  39_0402_5%  [R_0402]  87.34 19.93 0 top
RD7  39_0402_5%  [R_0402]  90.39 15.58 0 top
RD8  39_0402_5%  [R_0402]  90.39 16.4 0 top
RD9  39_0402_5%  [R_0402]  87.34 15.09 0 top
RD10  39_0402_5%  [R_0402]  90.39 13.95 0 top
RD11  39_0402_5%  [R_0402]  87.34 14.28 0 top
RD12  39_0402_5%  [R_0402]  87.34 16.7 0 top
RD13  39_0402_5%  [R_0402]  87.34 19.12 0 top
RD14  39_0402_5%  [R_0402]  91.47 12.38 0 top
RD15  39_0402_5%  [R_0402]  87.34 20.73 0 top
RD16  39_0402_5%  [R_0402]  87.34 15.89 0 top
RD17  39_0402_5%  [R_0402]  88.61 23.83 0 top
RD18  39_0402_5%  [R_0402]  90.39 21.02 0 top
RD19  39_0402_5%  [R_0402]  90.39 20.26 0 top
RD20  39_0402_5%  [R_0402]  90.39 22.67 0 top
RD21  39_0402_5%  [R_0402]  87.34 21.54 0 top
RD22  39_0402_5%  [R_0402]  90.39 21.85 0 top
RD23  39_0402_5%  [R_0402]  87.34 22.34 0 top
RD24  39_0402_5%  [R_0402]  87.34 18.31 0 top
RD25  39_0402_5%  [R_0402]  90.39 17.23 0 top
RD26  39_0402_5%  [R_0402]  90.39 18.05 0 top
RD27  39_0402_5%  [R_0402]  90.39 18.83 0 top
RD28  39_0402_5%  [R_0402]  90.4 23.5 0 top
RD29  39_0402_5%  [R_0402]  90.4 24.26 0 top
RD30  0_0201_5%  [R_0201]  104.91 55.83 0 top
RD31  0_0201_5%  [R_0201]  103.7 55.83 0 top
RD32  1K_0402_1%  [R_0402]  93.41 19.64 0 bottom
RD33  0_0201_5%  [R_0201]  105.2 21.33 270 bottom
RD34  0_0201_5%  [R_0201]  115.57 22.14 90 bottom
RD35  240_0201_1%  [R_0201]  104.63 20.74 90 bottom
RD36  240_0201_1%  [R_0201]  116.13 22.73 270 bottom
RD37  1K_0402_1%  [R_0402]  94.35 18.19 180 bottom
RD38  0_0201_5%  [R_0201]  126.93 31.15 0 top
RD39  0_0201_5%  [R_0201]  139.79 25.98 90 top
RD40  240_0201_1%  [R_0201]  127.51 30.59 180 top
RD41  240_0201_1%  [R_0201]  140.38 26.56 270 top
RD42  1K_0402_5%  [R_0402]  37.1 18.98 180 top
RD43  39_0402_5%  [R_0402]  35.14 21.75 270 bottom
RD44  39_0402_5%  [R_0402]  34.11 30.24 0 top
RD45  39_0402_5%  [R_0402]  34.11 31.01 0 top
RD46  1K_0402_1%  [R_0402]  47.52 18.94 270 top
RD47  1K_0402_1%  [R_0402]  48.48 19.56 90 bottom
RD48  240_0201_1%  [R_0201]  46.51 37.01 270 top
RD49  240_0201_1%  [R_0201]  58.53 35.58 180 top
RD50  240_0201_1%  [R_0201]  72.47 33.17 180 top
RD51  240_0201_1%  [R_0201]  85.61 28.21 180 top
RD52  0_0201_5%  [R_0201]  45.93 36.43 90 top
RD53  0_0201_5%  [R_0201]  57.94 36.14 0 top
RD54  0_0201_5%  [R_0201]  71.89 33.8 0 top
RD55  0_0201_5%  [R_0201]  86.02 29.86 270 top
RD56  39_0402_5%  [R_0402]  31.06 23.45 0 top
RD57  39_0402_5%  [R_0402]  31.06 24.21 0 top
RD58  39_0402_5%  [R_0402]  31.06 22.69 0 top
RD59  39_0402_5%  [R_0402]  34.97 24.49 180 top
RD60  39_0402_5%  [R_0402]  34.97 23.73 180 top
RD61  39_0402_5%  [R_0402]  34.97 22.2 180 top
RD62  39_0402_5%  [R_0402]  34.97 22.97 180 top
RD63  39_0402_5%  [R_0402]  31.06 21.93 0 top
RD64  39_0402_5%  [R_0402]  34.97 20.66 180 top
RD65  39_0402_5%  [R_0402]  34.97 21.44 180 top
RD66  39_0402_5%  [R_0402]  34.97 25.25 180 top
RD67  39_0402_5%  [R_0402]  34.03 18.75 0 top
RD68  39_0402_5%  [R_0402]  31.06 26.5 0 top
RD69  39_0402_5%  [R_0402]  34.03 19.54 0 top
RD70  0_0201_5%  [R_0201]  104.5 47.43 0 top
RD71  39_0402_5%  [R_0402]  35.02 29.42 180 top
RD72  39_0402_5%  [R_0402]  31.06 28.09 0 top
RD73  39_0402_5%  [R_0402]  31.06 28.85 0 top
RD74  39_0402_5%  [R_0402]  31.06 29.61 0 top
RD75  39_0402_5%  [R_0402]  35.02 27.89 180 top
RD76  39_0402_5%  [R_0402]  31.06 30.37 0 top
RD77  39_0402_5%  [R_0402]  35.02 28.66 180 top
RD78  39_0402_5%  [R_0402]  31.06 24.97 0 top
RD79  39_0402_5%  [R_0402]  31.06 25.74 0 top
RD80  39_0402_5%  [R_0402]  31.06 27.26 0 top
RD81  39_0402_5%  [R_0402]  35.02 27.08 180 top
RD82  0_0201_5%  [R_0201]  105.16 48.09 0 top
RF2  0_0603_5%  [R0603_0OHM]  187.18 52.66 90 top
RFP2  0_0402_5%  [R0402_0OHM]  105.44 7.36 90 top
RFP3  10K_0402_5%  [R_0402]  104.63 7.36 90 top
RFP4  10K_0402_5%  [R_0402]  105.52 9.19 0 top
RFP5  100K_0402_5%  [R_0402]  112.17 10.88 0 bottom
RFP6  0_0402_5%  [R0402_0OHM]  100.8 7.38 0 top
RFP8  0_0402_5%  [R_0402]  104.63 9.16 90 top
RFP9  0_0402_5%  [R0402_0OHM]  111.74 9.12 270 bottom
RFP10  0_0402_5%  [R_0402]  112.56 8.21 90 bottom
RFP11  0_0402_5%  [R_0402]  101.51 9.02 90 top
RFP12  0_0402_5%  [R0402_0OHM]  100.69 9.02 90 top
RH4  499_0201_1%  [R_0201]  19.45 64.14 270 bottom
RH5  499_0201_1%  [R_0201]  19.45 64.72 90 bottom
RH6  499_0201_1%  [R_0201]  20.02 65.78 270 bottom
RH7  499_0201_1%  [R_0201]  20.02 66.36 90 bottom
RH8  499_0201_1%  [R_0201]  19.45 67.58 270 bottom
RH9  499_0201_1%  [R_0201]  19.45 68.17 90 bottom
RH10  499_0201_1%  [R_0201]  20.01 69.03 270 bottom
RH11  499_0201_1%  [R_0201]  20.01 69.61 90 bottom
RH13  1M_0402_5%  [R_0402]  16.23 70.3 90 top
RH16  100K_0402_5%  [R_0402]  16.23 72.01 90 top
RH23  4.7K_0402_5%  [R_0402]  26.64 71.86 270 bottom
RH24  4.7K_0402_5%  [R_0402]  26.64 72.72 90 bottom
RH25  2.2K_0402_5%  [R_0402]  20.4 70.88 180 bottom
RH26  2.2K_0402_5%  [R_0402]  20.4 72.08 180 bottom
RHDT1  1K_0402_5%  [R_0402]  143.11 44.33 90 bottom
RHDT2  1K_0402_5%  [R_0402]  154.41 54.36 90 bottom
RHDT3  1K_0402_5%  [R_0402]  153.14 54.36 90 bottom
RHDT4  1K_0402_5%  [R_0402]  151.87 54.36 90 bottom
RHDT5  1K_0402_5%  [R_0402]  144.63 54.36 90 bottom
RHDT6  33_0402_5%  [R_0402]  149.32 44.79 90 bottom
RHDT7  10K_0402_5%  [R_0402]  148.02 44.85 90 bottom
RHDT8  10K_0402_5%  [R_0402]  146.52 45.75 180 bottom
RHDT9  10K_0402_5%  [R_0402]  144.86 44.86 90 bottom
RHDT10  0_0402_5%  [R_0402]  146.54 54.36 90 bottom
RHDT11  0_0402_5%  [R_0402]  150.09 54.36 90 bottom
RKBL1  10K_0402_5%  [R_0402]  143.69 12.08 0 top
RKBL2  30K_0402_1%  [R_0402]  144.61 12.92 180 top
RKBL3  100K_0402_5%  [R_0402]  137.13 9.67 0 bottom
RKBL4  330_0402_5%  [R_0402]  138.04 8.84 180 bottom
RKBL5  0_0201_5%  [R_0201]  137.04 8.15 0 bottom
RR64  0_0603_5%  [R_0603]  198.35 30.56 270 top
RR65  0_0603_5%  [R_0603]  168.95 28.91 180 top
RS3  866_0402_1%  [R_0402]  12.88 94.9 180 bottom
RS4  523_0402_1%  [R_0402]  12.88 94.13 180 bottom
RS5  866_0402_1%  [R_0402]  20.41 58.58 0 bottom
RS4030  100K_0402_5%  [R_0402]  37.1 50.13 90 bottom
RS4031  100K_0402_5%  [R_0402]  39.92 48.91 270 bottom
RSD3  100K_0402_5%  [R_0402]  37.38 46.61 90 bottom
RSD7  100K_0402_5%  [R_0402]  66.91 59.28 270 top
RSD8  0_0402_5%  [R_0402]  36.62 46.61 90 bottom
RSD9  0_0402_5%  [R_0402]  66.91 60.01 90 top
RSD12  150K_0402_5%  [R_0402]  34.6 53.18 180 bottom
RSD13  150K_0402_5%  [R_0402]  40.72 47.96 270 bottom
RSD16  0_0402_5%  [R0402_0OHM]  32.95 46.44 180 top
RSD17  0_0805_5%  [R_0805]  30.38 51.87 270 bottom
RT22  10K_0402_5%  [R_0402]  35.6 79.19 90 top
RT23  10K_0402_1%  [R_0402]  36.4 80.05 270 top
RT24  0_0402_5%  [R_0402]  37.01 88.41 180 top
RT25  100K_0402_5%  [R_0402]  33.23 85.59 0 top
RT26  100K_0402_5%  [R_0402]  33.23 86.78 0 top
RT27  2.2_0805_1%  [R_0805]  33.86 82.1 270 top
RT28  200K_0402_1%  [R_0402-X]  32.59 82.06 180 top
RT29  100K_0402_5%  [R_0402]  62.59 85.76 270 top
RT30  6.2K_0402_1%  [R_0402]  39.35 80.08 270 top
RT35  0_0402_5%  [R_0402]  43.44 80.92 0 top
RT37  200K_0402_1%  [R_0402-X]  36.65 77.68 0 top
RT38  10K_0402_1%  [R_0402]  37.21 80.05 270 top
RT39  100K_0402_5%  [R_0402]  29.14 81.26 0 top
RT40  200K_0402_1%  [R_0402-X]  39 77.68 180 top
RT41  10K_0402_1%  [R_0402]  38.43 80.03 270 top
RT58  100K_0402_5%  [R_0402]  20.03 71.99 0 top
RT59  100K_0402_5%  [R_0402]  20.13 69.21 90 top
RT60  100K_0402_5%  [R_0402]  21.81 70.06 270 top
RT63  100K_0402_5%  [R_0402]  37.85 88.41 0 top
RT66  174K_0402_1%  [R_0402]  29.25 70.31 0 top
RT67  27K_0402_5%  [R_0402]  29.38 69.49 270 top
RT69  100_0805_1%  [R_0805]  20.23 80.5 270 top
RT70  100K_0402_5%  [R_0402]  44.61 75.2 0 top
RT72  10K_0402_1%  [R_0402]  42.83 87.9 0 top
RT73  10K_0402_1%  [R_0402]  42.83 87.14 0 top
RT74  10K_0402_1%  [R_0402]  42.8 85.41 0 top
RT75  100K_0402_1%  [R_0402-X]  11.84 30.88 0 bottom
RT85  10K_0402_1%  [R_0402]  34.16 77.53 270 bottom
RT86  100K_0402_5%  [R_0402]  21 70.07 270 top
RT89  1K_0402_5%  [R_0402]  32.36 72.93 270 top
RT91  100K_0402_5%  [R_0402]  31.72 80.28 0 top
RT92  54.9K_0402_1%  [R_0402]  28.55 79.13 90 top
RTP2  4.7K_0402_5%  [R_0402]  123.68 10.61 90 bottom
RTP3  0_0402_5%  [R0402_0OHM]  133.53 13.04 180 bottom
RTP4  0_0402_5%  [R0402_0OHM]  183.11 22.45 270 top
RTP5  10K_0402_5%  [R_0402]  118.06 8.54 180 bottom
RTP6  30K_0402_1%  [R_0402]  117.15 7.71 0 bottom
RTP7  0_0402_5%  [R_0402]  123.68 7.43 90 bottom
RTP8  0_0402_5%  [R_0402]  118.04 9.87 180 bottom
RTP16  0_0402_5%  [R0402_0OHM]  115.43 8.54 0 bottom
RTS7  10K_0402_5%  [R_0402]  180.89 51.41 90 bottom
RTS8  0_0402_5%  [R0402_0OHM]  176.57 54.83 0 bottom
RUS1  10K_0402_5%  [R_0402]  188.56 20.24 0 top
RUS2  10K_0402_5%  [R_0402]  189.91 26.89 270 top
RUS3  0_0402_5%  [R_0402]  193.32 22.5 0 top
RUS4  10K_0402_5%  [R_0402]  186.4 23.58 0 top
RUS6  2.7M_0402_1%  [R_0402]  193.64 23.27 0 top
RUS7  24.9K_0402_1%  [R_0402]  193.64 24.06 0 top
RUS8  10K_0402_5%  [R_0402]  187.32 24.34 180 top
RUS9  0_0402_5%  [R0402_0OHM]  190.77 19 270 top
RUS10  0_0402_5%  [R0402_0OHM]  191.58 19.03 270 top
RUS11  0_0402_5%  [R0402_0OHM]  186.41 21.3 270 top
RUS12  0_0402_5%  [R0402_0OHM]  185.65 21.3 270 top
RUS13  0_0402_5%  [R_0402]  200.7 19.32 90 top
RWL2  0_0402_5%  [R0402_0OHM]  167.19 33.42 180 top
RWL4  0_0402_5%  [R0402_0OHM]  169.98 41.04 180 top
RWL5  0_0402_5%  [R0402_0OHM]  170.04 38.82 180 top
RWL6  0_0402_5%  [R0402_0OHM]  169.73 36.77 180 top
RWL7  0_0402_5%  [R0402_0OHM]  171.44 29.67 0 top
RWL8  0_0402_5%  [R0402_0OHM]  169.7 34.84 180 top
RWL9  0_0402_5%  [R0402_0OHM]  169.7 33.95 180 top
RWL12  100K_0402_5%  [R_0402]  171.89 36.77 180 top
RWL14  0_0402_5%  [R_0402]  166.27 32.53 0 top
RWL15  0_0402_5%  [R0402_0OHM]  169.15 56.65 180 bottom
RWL17  100K_0402_5%  [R_0402]  171.54 34.5 0 top
RWL18  0_0402_5%  [R_0402]  171.54 35.26 0 top
RWL19  0_0805_5%  [R0805_0OHM]  171.34 53.15 270 bottom
SW1  TBF313KQR_5P  [SW_TBF313KQR_5P]  2.89 45.2 90 top
T1  -  [TPC12]  126.79 74.88 180 bottom
T2  -  [TPC12]  128.87 74.83 180 bottom
T4  -  [TPC12]  91.66 56.41 0 top
T5  -  [TPC12]  93.26 55.83 0 top
T6  -  [TPC12]  91.8 57.68 0 top
T7  -  [TPC12]  91.8 53.93 0 top
T8  -  [TPC12]  88.24 56.66 0 top
T9  -  [TPC12]  113.33 70.46 0 top
T10  -  [TPC12]  112.37 59.33 0 top
T11  -  [TPC12]  110.4 59.33 0 top
T12  -  [TPC12]  113.29 71.91 0 top
T13  -  [TPC12]  95.55 57.55 0 top
T14  -  [TPC12]  95.61 58.88 0 top
T15  -  [TPC12]  94.28 59.14 0 top
T16  -  [TPC12]  88.88 59.64 0 top
T17  -  [TPC12]  128.06 69.14 180 bottom
T24  -  [TPC12]  182.73 49.42 0 top
T2403  PAD~D  [TPC12]  28.05 69.87 0 top
T2412  -  [TPC12]  87.93 58.18 0 top
T2413  -  [TPC12]  142.85 72.47 180 bottom
T2414  -  [TPC12]  113.39 66.82 0 top
U2  U74AHC1G08G-AL5-R_SOT353-5  [MC74VHC1G08DFT2G_SC70-5]  57.65 76.02 180 top
U5  EM5203AJ-20 SOT23 5P  [SY6288C20AAC_SOT23-5]  50.52 94.87 180 bottom
U7  SN1702001RTER_QFN16_3X3  [TPS2546RTER_QFN16_3X3-S]  191.23 24.58 180 top
U9  G524B2T11U_SOT23-5  [SY6288D20AAC_SOT23-5]  198.48 21.29 0 top
U10  S IC JW7110DFNC#TRPBF DFN14 DUAL LOAD SW  [EM5209VF_DFN14_3X2]  51.88 88.88 180 bottom
U19  -  [EM5201V_DFN8_3X3]  154.77 74.47 315 bottom
U20  -  [NC7WV07P6X_SC70-6]  147.66 56.28 0 bottom
UA1  -  [ALC3287-CG_MQFN48_6X6]  11.42 32.81 90 bottom
UC1  FP6_BGA1140  [FP6_BGA_1140P-T]  90.08 75.3 270 bottom
UC2  W25Q128JWSIQ_SO8  [W25Q128FWSIQ_SO8]  136.88 52.41 0 bottom
UC6  74AUP1G07GW_SC70-5  [SN74LVC1G07DCKR_SC70-5]  78.45 62.84 0 top
UC7  74AUP1G07GW_SC70-5  [SN74LVC1G07DCKR_SC70-5]  169.28 44.52 270 top
UC8  MC74VHC1G08DFT2G SC70 5P  [NC7SZ08P5X_NL_SC70-5]  165.97 36.34 270 top
UC22  74AUP1G07GW_SC70-5  [SN74LVC1G07DCKR_SC70-5]  140.2 78.65 180 bottom
UC23  MC74VHC1G08DFT2G SC70 5P  [NC7SZ08P5X_NL_SC70-5]  165.59 29.99 270 top
UD1  K4AAG165WA-BCWE_FBGA96  [K4AAG165WA-BCWE_FBGA_96P]  95.83 25.56 0 top
UD2  K4AAG165WA-BCWE_FBGA96  [K4AAG165WA-BCWE_FBGA_96P]  107.15 25.56 0 top
UD3  K4AAG165WA-BCWE_FBGA96  [K4AAG165WA-BCWE_FBGA_96P]  118.67 28.48 0 top
UD4  K4AAG165WA-BCWE_FBGA96  [K4AAG165WA-BCWE_FBGA_96P]  129.99 28.49 0 top
UD5  K4AAG165WA-BCWE_FBGA96  [K4AAG165WA-BCWE_FBGA_96P]  38.43 33.08 0 top
UD6  K4AAG165WA-BCWE_FBGA96  [K4AAG165WA-BCWE_FBGA_96P]  49.74 33.08 0 top
UD7  K4AAG165WA-BCWE_FBGA96  [K4AAG165WA-BCWE_FBGA_96P]  62.08 33.08 0 top
UD8  K4AAG165WA-BCWE_FBGA96  [K4AAG165WA-BCWE_FBGA_96P]  75.25 31.08 0 top
UEC1  -  [KB9022QD_LQFP128_14X14]  175.57 43.63 0 top
UH1  -  [AP2330W-7_SC59-3]  20.61 74.31 90 bottom
USD1  MC74VHC1G08DFT2G_SC70-5  [SN74AHC1G08DCKR_SC70-5]  35.48 48.1 270 bottom
USD2  MC74VHC1G08DFT2G_SC70-5  [SN74AHC1G08DCKR_SC70-5]  69.21 60.73 180 top
UT1  -  [RTS5457V-GR_QFN40_5X5]  40.39 86.92 270 top
UT2  SN1710033RUKR_WQFN20_3X3  [TPD6S300ARUKR_WQFN20_3X3]  26.98 85.86 0 top
UT4  S IC DPS1155FEA-13-01 V-QFN3025 20P_3X2P5  [DPS1155FEA_V-QFN3025-20_3X2P5]  26.62 69.18 180 top
UT6  -  [DPS1113FIA-13_QFN18_4X4]  27.43 74.04 90 top
UTS1  -  [F75305M_MSOP10]  175.18 50.26 90 bottom
UWL1  -  [G524B2T11U_SOT23-5]  169.51 52.29 180 bottom
UWL22  MC74VHC1G08DFT2G_SC70-5  [SN74AHC1G08DCKR_SC70-5]  173.59 32.26 90 top
YC1  48MHZ_8PF_7V48000010  [Y_X3S048000D81H-W_4P]  133.32 80.5 0 bottom
YC2  32.768KHZ_9PF_X1A000141000200  [Y_X1A000141000200_2P]  127.14 79.76 0 top

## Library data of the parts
C1 C4 C8-C13 C67 C70 C71 C74 C77 C80 C204 C229 C230 C233 C235 C237 C239 C241 C243 C249-C253 C256 C258 C266 C269 C316 CA10 CA11 CA13 CA20-CA22 CA24 CA25 CA50-CA52 CC9-CC12 CC22 CC26 CC32 CC43 CC44 CC55-CC62 CC65-CC67 CC69 CC71 CC72 CC74 CC76 CC77 CC79 CC80 CC82 CC114 CD3-CD7 CD34 CD36 CD38 CD40 CD42 CD43 CD45 CD46 CD48 CD49 CD51 CD52 CD54-CD58 CD91-CD95 CD97 CD99-CD102 CD104 CD105 CF2 CF5-CF10 CF13 CFP1-CFP4 CH1-CH10 CKBL2 CSD2 CSD6 CSD10 CSD12 CT35-CT38 CT43-CT45 CT47 CT49 CT51 CT58 CT72 CTP1 CTP5 CTP7 CTS5 CUS4 CWL2 CWL9 CWL61 = C_0201
C3 C68 C69 C72 C73 C75 C76 C78 C79 C84 C231 C232 C234 C236 C238 C240 C242 C255 C257 C259-C261 C265 C267 C268 C317 C318 CA1-CA9 CA12 CA14-CA19 CA28 CA30-CA33 CA35 CC1-CC8 CC17-CC20 CC23 CC24 CC27-CC31 CC33 CC45-CC51 CC63 CC78 CC81 CC105-CC113 CD1 CD2 CD8-CD33 CD35 CD37 CD39 CD41 CD44 CD47 CD50 CD53 CD59-CD90 CD96 CD98 CD103 CD106 CD109-CD114 CF1 CF3 CF4 CF11 CF12 CH11-CH14 CHDT1-CHDT3 CKBL1 CKBL3 CSD1 CSD3-CSD5 CSD7 CSD8 CT34 CT46 CT48 CT50 CT52 CT54-CT57 CT59 CT68 CT70 CT71 CT73 CT74 CT76-CT78 CTP2-CTP4 CTS1-CTS4 CTS6 CTS7 CUS1-CUS3 CWL1 PC10 PC11 PC251 PC255-PC257 PC301-PC303 PC310-PC313 PC501 PC506-PC508 PC517-PC522 PC601 PC603 PC604 PC612-PC615 PC623 PC715-PC717 PC719 PC724 PC726 PC801 PC802 PC806-PC813 PC816 PC817 PC821 PC822 PC825-PC833 PC838 PC842-PC844 PC849-PC855 PC1808 PC9056-PC9071 PC9081 PC9082 PC9102 PC9103 PC9119 PCB1 PCB2 PCB7-PCB9 PCB11 PCB12 PCB16 PCB18-PCB25 PCB28-PCB34 PCD1-PCD6 PCM2 PCM4 PCM5 PCM10-PCM14 PCM17-PCM19 PCS1 = C_0402
C7 PCB15 = C_0805
CC35-CC40 CC52-CC54 CC64 CC68 CC70 CC73 CC75 CC115-CC119 CD107 CD108 CT53 CT69 CT75 PC253 PC304-PC309 PC502-PC505 PC509-PC516 PC602 PC605-PC611 PC622 PC718 PC803-PC805 PC814 PC815 PC818 PC819 PC824 PC839-PC841 PC845-PC848 PC1807 PC9001-PC9020 PC9029-PC9053 PC9104-PC9112 PCB3-PCB6 PCB10 PCB13 PCB14 PCB17 PCB26 PCB27 PCB35 PCM1 PCM3 PCM6-PCM9 PCM15 PCM16 = C_0603
CLRP1 JP1 JP2 = SHORTPADS: User Part Number: PART#
D6 DA2 DT1 DT16 = AZC099-04SPR7G_SOT23-6
D33 DFP1 DTP1 = PSOT24C_SOT23-3
DA3 DA4 = AZ5125-02SPR7G_SOT23-3
DH1-DH3 = YSCLAMP0524P_SLP2510P8-10-9
DT6 = PESD24VS2UT_SOT23-3
DT7 DT8 = PUSB3FR4_DFN2510A10-10
DT15 = NSR20F30NXT5G_DSN2-2
FD1-FD4 = FIDUCIAL_C40M80
H1-H3 H11 = H_3P3
H5 H7 H18 = H_3P2
H8 H14 = H_3P1X2P1N
H10 H13 H15 = H_2P3
H12 = H_3P5
H16 = H_2P8
H17 = H_2P1N
J1 J2 J5 J6 PJ251 PJ252 PJ301 PJ604 PJ1803 PJ1804 PJM1 = JUMP_43X79
JBATT1 = ACES_60757-00802-001_8P-T
JDCIN1 = ACES_50278-00401-001_4P
JEDP1 = CVILU_CVS3402M1RM-NH_40P
JFAN2 = JXT_WB201H-004G10M_4P
JFP1 JTP1 = ACES_51522-00801-001_8P
JHDMI1 = LOTES_AHDM0064-P001A_19P
JHDT1 = SAMTE_ASP-136446-07-B_20P-T
JIO1 = HRS_TF31-40S-0P5SH-800_40P
JKB2 = ACES_51612-0340M-P01_34P-T
JKBL1 = ACES_51524-00401-001_4P
JP3 = YUQIU_1603046-01611_6P
JSPK1 = ACES_50271-0040N-001_4P
JSSD1 JSSD2 = BELLW_80159-3221_67P
JUSBC2 = DRAPH_UB11245-B200B-1H_24P-S
JWLAN1 = BELLW_80152-3221_67P
L1 L2 = MURAT_BLM15AX300SN1D_2P
LED2 = LED_LTW-C193TS5-C_2P
LED3 = LED_LTST-C191KFKT-2CA_2P
LED4 = LED_LTW-110DC5-C_3P
LH1-LH4 = INPAQ_HCM1012GH900BP_4P
LT1 = MURAT_DLM0NSN900HY2D_4P
PC820 PC834 = C_6P3X4P5
PC9021 PC9096 PC9115-PC9117 = C_D7
PC9094 PC9095 PC9098 PC9118 = C_X
PC9097 PC9099 PC9100 = C_D2
PD2 = RB751V-40_SOD323-2
PDB1 = BAT54CW_SOT323-3
PDD1 = BZT52-B5V1S_SOD323-2
PDM1 = D_SOD323-2
PF2 = F_F1206HB12V024TM
PFD1 PFS1 = F_F1206HI7000V024TM
PH1 PH801 PH802 PR11-PR15 PR252 PR254 PR256 PR303 PR304 PR503-PR507 PR509 PR511 PR512 PR605-PR607 PR609-PR611 PR621-PR623 PR716 PR719 PR801 PR802 PR805-PR807 PR809-PR811 PR816 PR818 PR819 PR821-PR823 PR825-PR837 PR841-PR843 PR845 PR856-PR859 PR871 PR1808 PR1809 PR1811 PR1812 PR1814 PR1815 PR1818 PR1819 PRB2 PRB3 PRB5-PRB7 PRB13 PRB16-PRB31 PRB33 PRB34 PRD1-PRD9 PRM2 PRM5 PRM9 PRM10 PRM12-PRM14 PRS1 PRS2 PRS4-PRS6 R7 R8 R54-R60 R62-R70 R74 R185 R201 R265-R267 R273 R274 R360 R2752 R4006 R4007 R4010-R4012 R4014 R4015 R4020 R4022-R4026 RA2 RA4 RA9-RA11 RA15-RA18 RA24 RA27 RA29 RA30 RA51 RA54 RA55 RA57 RA58 RA60 RA61 RC1 RC2 RC4-RC6 RC8-RC18 RC22 RC24 RC25 RC28-RC31 RC34-RC36 RC45 RC47 RC48 RC50 RC53-RC57 RC59 RC60 RC62 RC63 RC65-RC72 RC74-RC87 RC89-RC99 RC107 RC111 RC112 RC115 RC119-RC124 RC560 RC561 RC568 RC569 RC574 RC593 RC598 RC601 RC602 RC605-RC611 RC614-RC616 RC618-RC621 RC624 RC625 RC628 RD1-RD6 RD8-RD29 RD32 RD37 RD42-RD47 RD56-RD69 RD71-RD81 RFP3-RFP5 RFP8 RFP10 RFP11 RH13 RH16 RH23-RH26 RHDT1-RHDT11 RKBL1-RKBL4 RS3-RS5 RS4030 RS4031 RSD3 RSD7-RSD9 RSD12 RSD13 RT22-RT26 RT29 RT30 RT35 RT38 RT39 RT41 RT58-RT60 RT63 RT66 RT67 RT70 RT72-RT74 RT85 RT86 RT89 RT91 RT92 RTP2 RTP5-RTP8 RTS7 RUS1-RUS4 RUS6-RUS8 RUS13 RWL12 RWL14 RWL17 RWL18 = R_0402
PJ302 PJ501 PJ502 PJ601 PJM2 = JUMP_43X118
PJ303 PJ503 PJM3 = JUMP_43X39
PL3 PL4 PL801 PL802 PLD11 = 5A_Z80_0805_2P
PL301 PLM1 = L_5X5X3_M
PL501 PL803-PL806 = L_7X7X3_M
PL602 = L_5X5X3_M_2P
PL1802 = TAI-T_TMPC0412HP-1R5M-Z02_2P
PLB1 = CYNTE_PCMB103T-2R2MS_2P
PQ601 PQB3 PQB4 = LSK3541G1ET2L_VMT3
PQ801 PQ802 PQ804 PQ805 = AON6962_DFN5X6D-8-7
PQB1 = AON6992_DFN5X6D-8-7
PQB2 = AON6994_DFN5X6D-8-7
PQB13 PQD11 PQD12 PQS11 PQS12 = Q_P_DFN33-8-5
PQD3 Q202 QA4 QC2 QH1 = 2N7002KDW_SOT363-6
PQD4 PQS3 = LBSS84LT1G_SOT23-3
PQD5 PQS4 = METR3906KW-G_SOT363-6
PQM1 = AON7408L_DFN8-5
PQM2 = AON7506_DFN3X3-8-5
PQS2 = L2N7002WT1G_SC70-3
PR8 PR10 PR603 PR803 PR817 PR838 R4000 RA1 RA3 RA5 RA6 RA19 RA34 RF2 = R0603_0OHM
PR9 PR804 PR812 PR820 PR839 PR853 PR860 PR1810 PRM6 PRM8 PRM11 R75 R337 RA59 RR64 RR65 = R_0603
PR251 PR301 PR501 PR508 PR510 PR601 PR604 PR713 PR720 PR815 PR844 PR846 PR847 PR1807 PR1813 PR1816 PR1817 PRB4 PRB10-PRB12 PRB32 PRM3 PRM4 R5 R6 R359 R3999 R4002 RA8 RA21-RA23 RA25 RA26 RA28 RA31-RA33 RC21 RC64 RC73 RC106 RC585 RC586 RC594 RC595 RC597 RC603 RC604 RC617 RC626 RC627 RFP2 RFP6 RFP9 RFP12 RSD16 RTP3 RTP4 RTP16 RTS8 RUS9-RUS12 RWL2 RWL4-RWL9 RWL15 = R0402_0OHM
PR302 PR602 PR808 PR824 PR840 PR855 PRB14 PRB15 PRM1 R4021 = R_1206
PR502 PRB8 RSD17 RT27 RT69 = R_0805
PRB1 PRB9 = R_1206_4P-D
PU251 = RT9059GQW_WDFN10_3X3
PU301 = SY8388BRHC_QFN16_2P5X2P5
PU501 = SY8288CRAC_QFN20_3X3
PU601 = SY8284RAC_QFN20_3X3
PU801 = RT3663BHGQW_WQFN52_6X6
PU802 = RT9610CGQW_WDFN8_2X2
PU1802 = SY8386RHC_QFN16_2P5X2P5
PUB1 = BQ25700ARSNR_QFN32_4X4
PUM1 = RT8207PGQW_WQFN20_3X3
Q5 = LBSS138LT1G_SOT23-3
Q146 QT2 = 2N7002KW_SOT323-3
Q201 Q208 Q209 QA1-QA3 QKBL1 QT3 QTP1 = ME2301DC-G_SOT23-3
Q206 Q207 QC1 = LBSS139WT1G_SC70-3
QH2 = 2N7002DW-T-R7_SOT363-6
QT1 = 2N7002_SOT23-3
QT4 = L2N7002WT1G_SC-70-3
QTS1-QTS3 = MMST3904-7-F_SOT323-3
R2 R9 RA12 RWL19 = R0805_0OHM
R358 = MURAT_BLM15PX221SN1D_2P
RA13 RA14 = MURAT_BLM15BD121SN1D_2P
RD7 = R_0402: signal model: R_0402_0_0402_5%
RD30 RD31 RD33-RD36 RD38-RD41 RD48-RD55 RD70 RD82 RH4-RH11 RKBL5 = R_0201
RT28 RT37 RT40 RT75 = R_0402-X
SW1 = SW_TBF313KQR_5P
T1 T2 T4-T17 T24 T2403 T2412-T2414 = TPC12
U2 = MC74VHC1G08DFT2G_SC70-5
U5 = SY6288C20AAC_SOT23-5
U7 = TPS2546RTER_QFN16_3X3-S
U9 = SY6288D20AAC_SOT23-5
U10 = EM5209VF_DFN14_3X2
U19 = EM5201V_DFN8_3X3
U20 = NC7WV07P6X_SC70-6
UA1 = ALC3287-CG_MQFN48_6X6
UC1 = FP6_BGA_1140P-T
UC2 = W25Q128FWSIQ_SO8
UC6 UC7 UC22 = SN74LVC1G07DCKR_SC70-5
UC8 UC23 = NC7SZ08P5X_NL_SC70-5
UD1-UD8 = K4AAG165WA-BCWE_FBGA_96P
UEC1 = KB9022QD_LQFP128_14X14
UH1 = AP2330W-7_SC59-3
USD1 USD2 UWL22 = SN74AHC1G08DCKR_SC70-5
UT1 = RTS5457V-GR_QFN40_5X5
UT2 = TPD6S300ARUKR_WQFN20_3X3
UT4 = DPS1155FEA_V-QFN3025-20_3X2P5
UT6 = DPS1113FIA-13_QFN18_4X4
UTS1 = F75305M_MSOP10
UWL1 = G524B2T11U_SOT23-5
YC1 = Y_X3S048000D81H-W_4P
YC2 = Y_X1A000141000200_2P

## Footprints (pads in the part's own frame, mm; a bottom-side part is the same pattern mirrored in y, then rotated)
2N7002_SOT23-3
  oval 1.016x1.524 smd: 1(0,0) 2(0.965,2.083) 3(-0.965,2.083)
2N7002DW-T-R7_SOT363-6
  oval 0.381x1.397 smd: 1(0,0) 2(0.65,0) 3(1.3,0) 4(1.3,1.725) 5(0.65,1.725) 6(0,1.725)
2N7002KDW_SOT363-6
  oval 0.356x0.889 smd: 1(0,0) 2(0.65,0) 3(1.3,0) 4(1.3,1.6) 5(0.65,1.6) 6(0,1.6)
2N7002KW_SOT323-3
  oval 0.66x0.864 smd: 1(0,0) 2(0.65,1.85) 3(-0.65,1.85)
5A_Z80_0805_2P
  rect 0.813x1.397 smd: 1(0,0) 2(1.702,0)
ACES_50271-0040N-001_4P
  oval 0.787x1.6 smd: 1(0,0) 2(-1.25,0) 3(-2.5,0) 4(-3.75,0)
  rect 2.108x2.997 smd: 5(2.55,-2.9) 6(-6.3,-2.9)
ACES_50278-00401-001_4P
  oval 0.787x1.905 smd: 1(0,0) 2(1.25,0) 3(2.5,0) 4(3.75,0)
  rect 1.295x3.353 smd: 5(-2.85,-4.925) 6(6.6,-4.925)
ACES_51522-00801-001_8P
  oval 0.305x1.295 smd: 1(0,0) 2(0.5,0) 3(1,0) 4(1.5,0) 5(2,0) 6(2.5,0) 7(3,0) 8(3.5,0)
  rect 2.489x1.905 smd: 9(5.65,-3.3) 10(-2.15,-3.3)
